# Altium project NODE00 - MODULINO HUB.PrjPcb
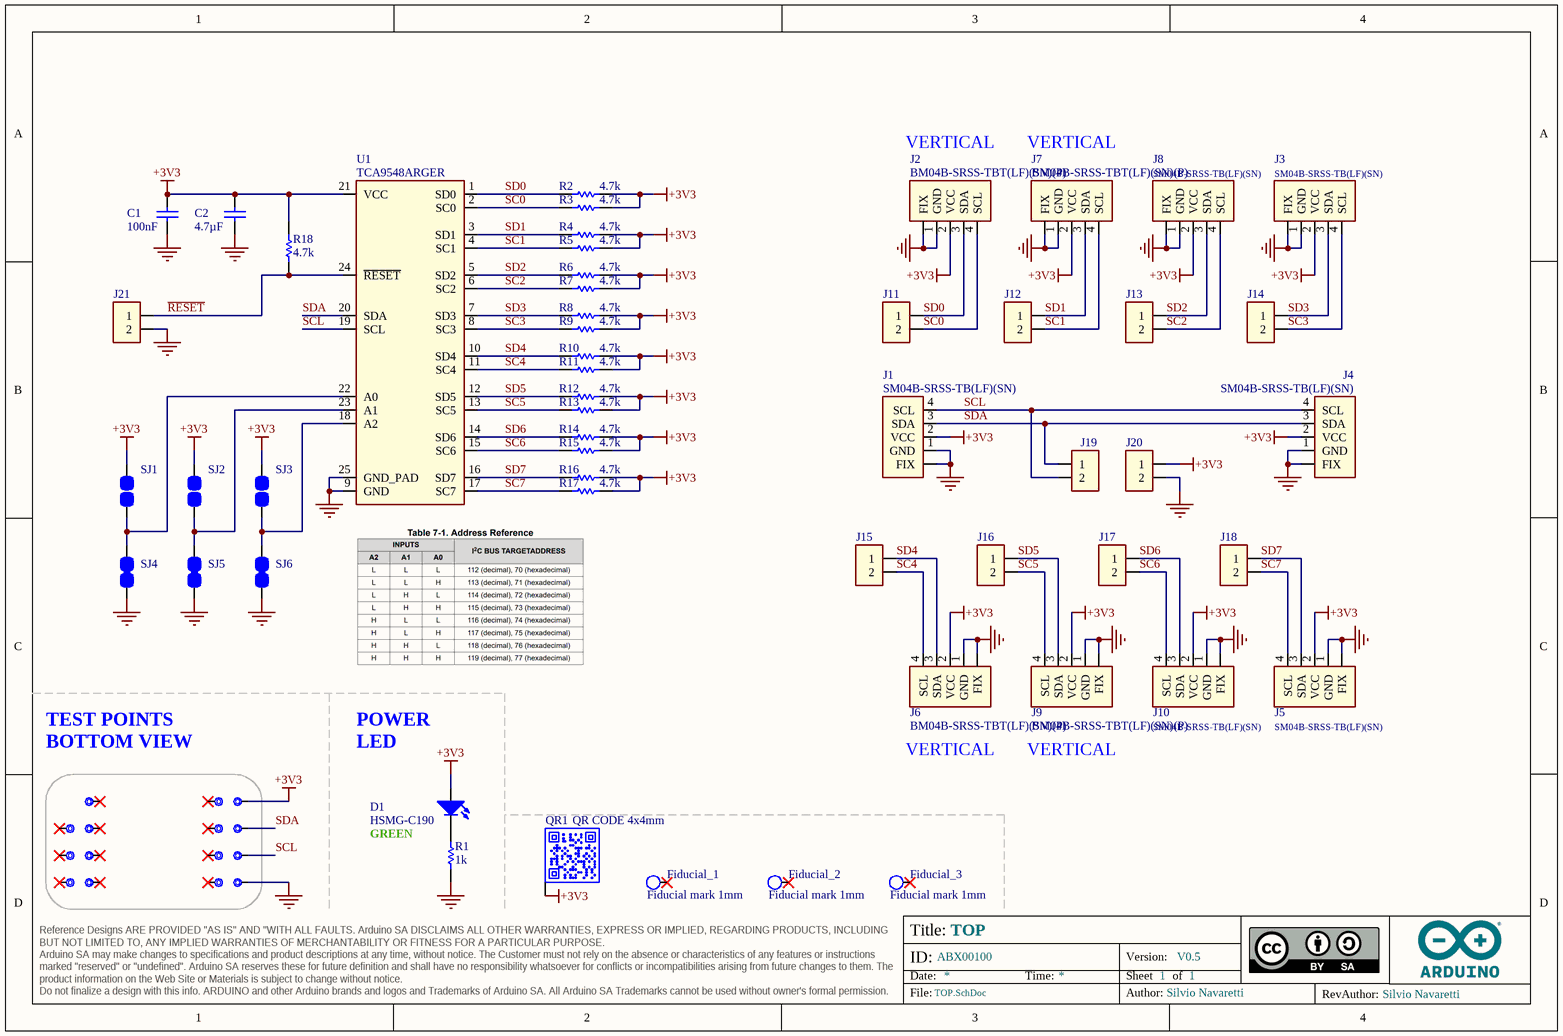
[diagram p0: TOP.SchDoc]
ASSEMBLY_BGA: _; ASSEMBLY_PRESSFIT: _; ASSEMBLY_SMD: X; ASSEMBLY_THT: _; BOARD_CODENAME: NODE00; BOARD_CODENAME_HW: NODE00 - HUB; BOARD_INFO_AUTHOR: Silvio Navaretti; BOARD_INFO_AUTHOR_REV: Silvio Navaretti; BOARD_INFO_Er: _; BOARD_INFO_FLEX: _; BOARD_INFO_FR4: X; BOARD_INFO_FR4_HTG: _; BOARD_INFO_IPC1: _; BOARD_INFO_IPC2: X; BOARD_INFO_IPC3: _; BOARD_INFO_IPC_NA: _; BOARD_INFO_NUMBER_OF_LAYERS: 2; BOARD_INFO_PCB_SIZE: 41.00x25.36mm; BOARD_INFO_POLYMIDE: _; BOARD_INFO_RIGID: X; BOARD_INFO_RIGID/FLEX: _; BOARD_INFO_TBD: _; BOARD_INFO_THICKNESS: 1.6mm; DRILLS_BLIND: _; DRILLS_BURIED: _; DRILLS_COPPER_FILLING: _; DRILLS_FULL: X; DRILLS_LASER: _; DRILLS_PRESSFIT: _; DRILLS_RESIN_FILLING: _; DRILLS_SLOT: _; DRILLS_SOLDER_FILLING: X; FINISH_ADJUSTMENTS: _; FINISH_EDGE_PLATING: _; FINISH_ENIG: _; FINISH_HAL: _; FINISH_HAL_LF: X; FINISH_NI/AU: _; FINISH_SILK_BOTTOM: X; FINISH_SILK_COLOR: WHITE; FINISH_SILK_TOP: X; FINISH_SN/PB: _; FINISH_SOLDERMASK_BOTTOM: X; FINISH_SOLDERMASK_COLOR: BLUE; FINISH_SOLDERMASK_PEELABLE_BOTTOM: _; FINISH_SOLDERMASK_PEELABLE_COLOR: _; FINISH_SOLDERMASK_PEELABLE_TOP: _; FINISH_SOLDERMASK_TOP: X; FINISH_TABS: _; FINISH_TBD: _; INSULATION_MIN_INNER: 0.15mm; INSULATION_MIN_OUTER: 0.15mm; PANEL_MILLING: X; PANEL_NOT_REQUESTED: _; PANEL_NUMBER_OF_FIGURES: 30; PANEL_PROVIDED: X; PANEL_REQUESTED: _; PANEL_SCORING: X; PANEL_SIZE: 262x221mm; PANEL_TABS: _; SKU: ABX00100; TRACK_MIN_WIDTH_INNER: 0.15mm; TRACK_MIN_WIDTH_OUTER: 0.15mm; Version: V0.5; VIA_1: _; VIA_1_HOLE_MM: _; VIA_1_PAD_MM: _; VIA_2: _; VIA_2_HOLE_MM: _; VIA_2_PAD_MM: _; VIA_3: _; VIA_3_HOLE_MM: _; VIA_3_PAD_MM: _; VIA_4: _; VIA_4_HOLE_MM: _; VIA_4_PAD_MM: _; VIA_5: _; VIA_5_HOLE_MM: _; VIA_5_PAD_MM: _; VIA_THROUGH: X; VIA_THROUGH_HOLE_MM: 0.3; VIA_THROUGH_PAD_MM: 0.6
1 sheet, 68 parts. Net scope: hierarchical (ports join the sheet entries above them; power ports are global).
Board files: PCB.PcbDoc, PANEL.PcbDoc

## Sheet TOP.SchDoc: TOP
size A4; Revision: V0.5; SheetNumber: 1; SheetTotal: 1

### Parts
3V3  Test point 1.00mm  [TP-1.00MM]  (value not drawn)  (no BOM)
C1  value 100nF  [CAP-0402]  (hidden comment: 0402B104K160CT)
C2  value 4.7µF  [CAP-0603]  (hidden comment: GRM188R61C475KAAJD)
D1  HSMG-C190  [LEDC1608X80N-AK]
Fiducial_1  Fiducial mark 1mm  [Fiducial mark 1mm-Footprint-1]  (no BOM)
Fiducial_2  Fiducial mark 1mm  [Fiducial mark 1mm-Footprint-1]  (no BOM)
Fiducial_3  Fiducial mark 1mm  [Fiducial mark 1mm-Footprint-1]  (no BOM)
GND  Test point 1.00mm  [TP-1.00MM]  (value not drawn)  (no BOM)
J1  SM04B-SRSS-TB(LF)(SN)  [SM04B-SRSS-TB(LF)(SN)-Footprint-1]
J2  BM04B-SRSS-TBT(LF)(SN)(P)  [BM04B-SRSS-TB]
J3  SM04B-SRSS-TB(LF)(SN)  [SM04B-SRSS-TB(LF)(SN)-Footprint-1]
J4  SM04B-SRSS-TB(LF)(SN)  [SM04B-SRSS-TB(LF)(SN)-Footprint-1]
J5  SM04B-SRSS-TB(LF)(SN)  [SM04B-SRSS-TB(LF)(SN)-Footprint-1]
J6  BM04B-SRSS-TBT(LF)(SN)(P)  [BM04B-SRSS-TB]
J7  BM04B-SRSS-TBT(LF)(SN)(P)  [BM04B-SRSS-TB]
J8  SM04B-SRSS-TB(LF)(SN)  [SM04B-SRSS-TB(LF)(SN)-Footprint-1]
J9  BM04B-SRSS-TBT(LF)(SN)(P)  [BM04B-SRSS-TB]
J10  SM04B-SRSS-TB(LF)(SN)  [SM04B-SRSS-TB(LF)(SN)-Footprint-1]
J11  HEADER TH 2.54mm VERT. 1x002POS  [PIN HEADER 2.54mm VERT. 1x2POS]  (value not drawn)  (no BOM)
J12  HEADER TH 2.54mm VERT. 1x002POS  [PIN HEADER 2.54mm VERT. 1x2POS]  (value not drawn)  (no BOM)
J13  HEADER TH 2.54mm VERT. 1x002POS  [PIN HEADER 2.54mm VERT. 1x2POS]  (value not drawn)  (no BOM)
J14  HEADER TH 2.54mm VERT. 1x002POS  [PIN HEADER 2.54mm VERT. 1x2POS]  (value not drawn)  (no BOM)
J15  HEADER TH 2.54mm VERT. 1x002POS  [PIN HEADER 2.54mm VERT. 1x2POS]  (value not drawn)  (no BOM)
J16  HEADER TH 2.54mm VERT. 1x002POS  [PIN HEADER 2.54mm VERT. 1x2POS]  (value not drawn)  (no BOM)
J17  HEADER TH 2.54mm VERT. 1x002POS  [PIN HEADER 2.54mm VERT. 1x2POS]  (value not drawn)  (no BOM)
J18  HEADER TH 2.54mm VERT. 1x002POS  [PIN HEADER 2.54mm VERT. 1x2POS]  (value not drawn)  (no BOM)
J19  HEADER TH 2.54mm VERT. 1x002POS  [PIN HEADER 2.54mm VERT. 1x2POS]  (value not drawn)  (no BOM)
J20  HEADER TH 2.54mm VERT. 1x002POS  [PIN HEADER 2.54mm VERT. 1x2POS]  (value not drawn)  (no BOM)
J21  HEADER TH 2.54mm VERT. 1x002POS  [PIN HEADER 2.54mm VERT. 1x2POS]  (value not drawn)  (no BOM)
NRST  Test point 1.00mm  [TP-1.00MM]  (value not drawn)  (no BOM)
PA6  Test point 1.00mm  [TP-1.00MM]  (value not drawn)  (no BOM)
PA7  Test point 1.00mm  [TP-1.00MM]  (value not drawn)  (no BOM)
PC14  Test point 1.00mm  [TP-1.00MM]  (value not drawn)  (no BOM)
PC15  Test point 1.00mm  [TP-1.00MM]  (value not drawn)  (no BOM)
QR1  QR CODE 4x4mm  [QR CODE 4x4mm]  (no BOM)
R1  value 1k  [RES-0402]  (hidden comment: CRCW04021K00FKEDC)
R2  value 4.7k  [RES-0402]  (hidden comment: RC0402FR-074K7L)
R3  value 4.7k  [RES-0402]  (hidden comment: RC0402FR-074K7L)
R4  value 4.7k  [RES-0402]  (hidden comment: RC0402FR-074K7L)
R5  value 4.7k  [RES-0402]  (hidden comment: RC0402FR-074K7L)
R6  value 4.7k  [RES-0402]  (hidden comment: RC0402FR-074K7L)
R7  value 4.7k  [RES-0402]  (hidden comment: RC0402FR-074K7L)
R8  value 4.7k  [RES-0402]  (hidden comment: RC0402FR-074K7L)
R9  value 4.7k  [RES-0402]  (hidden comment: RC0402FR-074K7L)
R10  value 4.7k  [RES-0402]  (hidden comment: RC0402FR-074K7L)
R11  value 4.7k  [RES-0402]  (hidden comment: RC0402FR-074K7L)
R12  value 4.7k  [RES-0402]  (hidden comment: RC0402FR-074K7L)
R13  value 4.7k  [RES-0402]  (hidden comment: RC0402FR-074K7L)
R14  value 4.7k  [RES-0402]  (hidden comment: RC0402FR-074K7L)
R15  value 4.7k  [RES-0402]  (hidden comment: RC0402FR-074K7L)
R16  value 4.7k  [RES-0402]  (hidden comment: RC0402FR-074K7L)
R17  value 4.7k  [RES-0402]  (hidden comment: RC0402FR-074K7L)
R18  value 4.7k  [RES-0402]  (hidden comment: RC0402FR-074K7L)
SCL  Test point 1.00mm  [TP-1.00MM]  (value not drawn)  (no BOM)
SDA  Test point 1.00mm  [TP-1.00MM]  (value not drawn)  (no BOM)
SJ1  SOLDER JUMPER OPEN 0603  [SJ]  (value not drawn)  (no BOM)
SJ2  SOLDER JUMPER OPEN 0603  [SJ]  (value not drawn)  (no BOM)
SJ3  SOLDER JUMPER OPEN 0603  [SJ]  (value not drawn)  (no BOM)
SJ4  SOLDER JUMPER CLOSED 0603  [SJ 0603 CLOSED]  (value not drawn)  (no BOM)
SJ5  SOLDER JUMPER CLOSED 0603  [SJ 0603 CLOSED]  (value not drawn)  (no BOM)
SJ6  SOLDER JUMPER CLOSED 0603  [SJ 0603 CLOSED]  (value not drawn)  (no BOM)
SWCLK  Test point 1.00mm  [TP-1.00MM]  (value not drawn)  (no BOM)
SWDIO  Test point 1.00mm  [TP-1.00MM]  (value not drawn)  (no BOM)
TP9  Test point 1.00mm  [TP-1.00MM]  (value not drawn)  (no BOM)
TP10  Test point 1.00mm  [TP-1.00MM]  (value not drawn)  (no BOM)
TP11  Test point 1.00mm  [TP-1.00MM]  (value not drawn)  (no BOM)
TP12  Test point 1.00mm  [TP-1.00MM]  (value not drawn)  (no BOM)
U1  TCA9548ARGER  [PQFN50P400X400X100_HS-25N]

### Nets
+3V3: 3V3.X C1.1 C2.2 D1.A J1.2(VCC) J2.2(VCC) J3.2(VCC) J4.2(VCC) J5.2(VCC) J6.2(VCC) J7.2(VCC) J8.2(VCC) J9.2(VCC) J10.2(VCC) J20.1 QR1.PAD R2.2 R3.2 R4.2 R5.2 R6.2 R7.2 R8.2 R9.2 R10.2 R11.2 R12.2 R13.2 R14.2 R15.2 R16.2 R17.2 R18.1 SJ1.1 SJ2.1 SJ3.1 U1.21(VCC)
GND: C1.2 C2.1 GND.X J1.1(GND) J1.FIX J2.1(GND) J2.FIX J3.1(GND) J3.FIX J4.1(GND) J4.FIX J5.1(GND) J5.FIX J6.1(GND) J6.FIX J7.1(GND) J7.FIX J8.1(GND) J8.FIX J9.1(GND) J9.FIX J10.1(GND) J10.FIX J20.2 J21.2 R1.1 SJ4.2 SJ5.2 SJ6.2 U1.9(GND) U1.25(GND_PAD)
~{RESET}: J21.1 R18.2 U1.24(~{RESET})  [project net ~{RESET}_1]
SC0: J2.4(SCL) J11.2 R3.1 U1.2(SC0)  [project net SC0_1]
SC1: J7.4(SCL) J12.2 R5.1 U1.4(SC1)  [project net SC1_1]
SC2: J8.4(SCL) J13.2 R7.1 U1.6(SC2)  [project net SC2_1]
SC3: J3.4(SCL) J14.2 R9.1 U1.8(SC3)  [project net SC3_1]
SC4: J6.4(SCL) J15.2 R11.1 U1.11(SC4)  [project net SC4_1]
SC5: J9.4(SCL) J16.2 R13.1 U1.13(SC5)  [project net SC5_1]
SC6: J10.4(SCL) J17.2 R15.1 U1.15(SC6)  [project net SC6_1]
SC7: J5.4(SCL) J18.2 R17.1 U1.17(SC7)  [project net SC7_1]
SCL: J1.4(SCL) J4.4(SCL) J19.2 SCL.X U1.19(SCL)  [project net SCL_1]
SD0: J2.3(SDA) J11.1 R2.1 U1.1(SD0)  [project net SD0_1]
SD1: J7.3(SDA) J12.1 R4.1 U1.3(SD1)  [project net SD1_1]
SD2: J8.3(SDA) J13.1 R6.1 U1.5(SD2)  [project net SD2_1]
SD3: J3.3(SDA) J14.1 R8.1 U1.7(SD3)  [project net SD3_1]
SD4: J6.3(SDA) J15.1 R10.1 U1.10(SD4)  [project net SD4_1]
SD5: J9.3(SDA) J16.1 R12.1 U1.12(SD5)  [project net SD5_1]
SD6: J10.3(SDA) J17.1 R14.1 U1.14(SD6)  [project net SD6_1]
SD7: J5.3(SDA) J18.1 R16.1 U1.16(SD7)  [project net SD7_1]
SDA: J1.3(SDA) J4.3(SDA) J19.1 SDA.X U1.20(SDA)  [project net SDA_1]
NetD1_C: D1.C R1.2
NetSJ1_2: SJ1.2 SJ4.1 U1.22(A0)
NetSJ2_2: SJ2.2 SJ5.1 U1.23(A1)
NetSJ3_2: SJ3.2 SJ6.1 U1.18(A2)

Not connected (* = marked no-connect by the designer): Fiducial_1 1*; Fiducial_2 1*; Fiducial_3 1*; NRST X*; PA6 X*; PA7 X*; PC14 X*; PC15 X*; SWCLK X*; SWDIO X*; TP9 X*; TP10 X*; TP11 X*; TP12 X*

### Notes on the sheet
- VERTICAL
- TEST POINTS BOTTOM VIEW
- (near D1) POWER LED
- GREEN

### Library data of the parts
3V3 GND NRST PA6 PA7 PC14 PC15 SCL SDA SWCLK SWDIO TP9-TP12 = UT0013-A.6: Manufacturer: This is not a component
C1 = C0012-A.15: CAP CHIP 0402 100nF 10% 16V X7R; Manufacturer: Walsin; Code Arduino: 0132
C2 = C0054-A.16: CAP CHIP 0603 4.7uF 10% 16V X5R; Manufacturer: Murata; Code Arduino: A5072
D1 = L0009-A.5: LED SMD 0603 GREEN/568 15mcd 120^; Manufacturer: Broadcom; Code Arduino: 2204
Fiducial_1-Fiducial_3 = UT0023-A.7: Fiducial mark 1mm clearance 2mm
J1 J3-J5 J8 J10 = J0005-A.2: CONN JST 4POS SIDE 1MM TIN QWIIC; Code Arduino: J0005
J2 J6 J7 J9 = J0478-A.3: CONN JST 4POS VERTICAL 1mm pitch, color neutral, suction tape, tin, QWIIC; Code Arduino: J0478
J11-J21 = J0238-A.5: Code Arduino: J0238
QR1 = QR-0001-A.5: QR CODE 4x4mm on layer 34 (This is not a component); Code Arduino: QRCODE_4x4mm
R1 = R0007-A.24: RES CHIP 0402 1k 1% 1/16W; Manufacturer: Vishay; Code Arduino: 0140; Power: 62.5mW; Temperature coefficient: 100ppm
R2-R18 = R0013-A.24: RES CHIP 0402 4k7 1% 1/16W; Manufacturer: YAGEO; Power: 62.5mW; Temperature coefficient: 200ppm; Code Arduino: 2196
SJ1-SJ3 = UT0038-A.5: Code Arduino: This is not a component
SJ4-SJ6 = UT0039-A.4: Code Arduino: This is not a component
U1 = U0170-A.3: IC I2C SWITCH 8CH with RST, 5V tolerant pins, 1V8 to 5V buses, VQFN24 4x4mm pitch 0.5mm; Manufacturer: Texas Instruments; Code Arduino: U0170

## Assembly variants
ABX00100: not fitted J11 J12 J13 J14 J15 J16 J17 J18 J19 J20 J21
